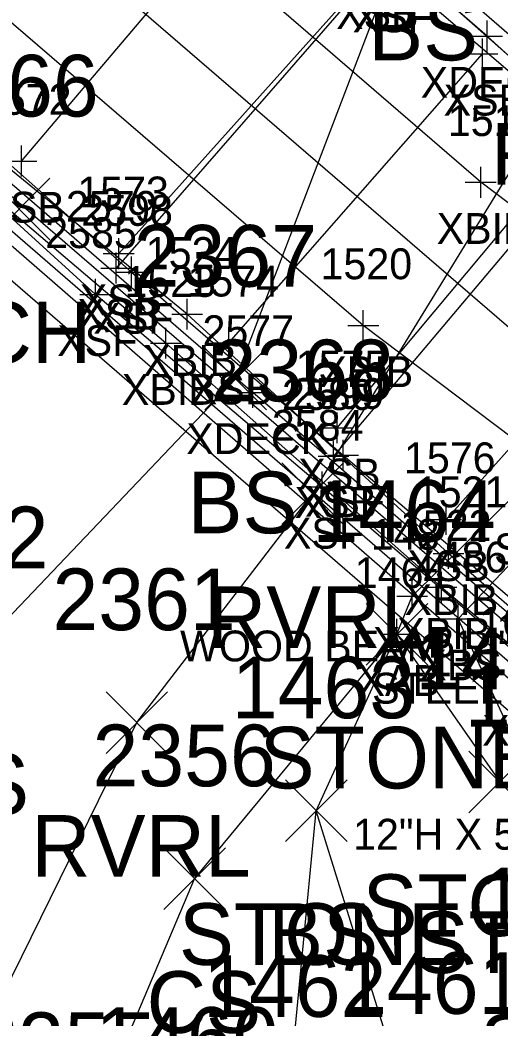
# Model space of a CAD drawing. Extents: x 1459992 to 1461532, y 647785 to 648535.
# Drawn here: x 1461331.07 to 1461346.66, y 648146.3 to 648178.67 of the extents above; entities that cross this region are included whole.
import ezdxf

# ---------------------------------------------------------------- set-up
doc = ezdxf.new("R2010")
doc.units = 0
for name, color, linetype in [('B_A', 7, 'Continuous'), ('B_C', 7, 'Continuous'), ('B_I', 7, 'Continuous'), ('B_TIC', 7, 'Continuous'), ('BB', 7, 'Continuous'), ('BDEFAULT', 7, 'Continuous'), ('BELB', 7, 'Continuous'), ('BSE', 7, 'Continuous'), ('BSUBM', 7, 'Continuous'), ('L_A', 7, 'Continuous'), ('L_I', 7, 'Continuous'), ('L_TIC', 7, 'Continuous'), ('LASF', 7, 'Continuous'), ('LAWE', 7, 'Continuous'), ('LELB', 7, 'Continuous')]:
    doc.layers.add(name, color=color, linetype=linetype)

msp = doc.modelspace()

# ---------------------------------------------------------------- linework, layer by layer
at = {"layer": 'B_TIC'}
for p, q in [((1461346.247, 648178.153), (1461346.322, 648178.153)), ((1461346.094, 648177.574), (1461346.17, 648177.574)), ((1461331.123, 648174.098), (1461331.199, 648174.098)), ((1461346.037, 648173.409), (1461346.112, 648173.409)), ((1461334.283, 648171.093), (1461334.358, 648171.093)), ((1461334.203, 648170.626), (1461334.279, 648170.626)), ((1461334.699, 648170.496), (1461334.775, 648170.496)), ((1461333.527, 648169.773), (1461333.602, 648169.773)), ((1461336.509, 648169.128), (1461336.584, 648169.128)), ((1461342.226, 648168.764), (1461342.301, 648168.764)), ((1461335.813, 648168.189), (1461335.889, 648168.189)), ((1461337.857, 648168.203), (1461337.933, 648168.203)), ((1461338.635, 648166.593), (1461338.71, 648166.593)), ((1461338.635, 648166.593), (1461338.71, 648166.593)), ((1461341.375, 648165.445), (1461341.451, 648165.445)), ((1461341.257, 648164.521), (1461341.333, 648164.521)), ((1461341.567, 648164.557), (1461341.642, 648164.557)), ((1461340.885, 648163.524), (1461340.961, 648163.524)), ((1461344.918, 648162.471), (1461344.993, 648162.471)), ((1461344.992, 648161.367), (1461345.068, 648161.367)), ((1461344.992, 648161.367), (1461345.068, 648161.367)), ((1461344.759, 648160.272), (1461344.834, 648160.272)), ((1461344.759, 648160.272), (1461344.834, 648160.272)), ((1461343.814, 648159.987), (1461343.889, 648159.987)), ((1461345.304, 648159.251), (1461345.379, 648159.251)), ((1461343.317, 648158.745), (1461343.392, 648158.745))]:
    msp.add_line(p, q, dxfattribs=at)
for points in [[(1461346.243, 648177.653), (1461346.243, 648178.653)], [(1461345.743, 648178.153), (1461346.743, 648178.153)], [(1461346.091, 648177.074), (1461346.091, 648178.074)], [(1461345.591, 648177.574), (1461346.591, 648177.574)], [(1461331.12, 648173.598), (1461331.12, 648174.598)], [(1461330.62, 648174.098), (1461331.62, 648174.098)], [(1461346.033, 648172.909), (1461346.033, 648173.909)], [(1461345.533, 648173.409), (1461346.533, 648173.409)], [(1461334.279, 648170.593), (1461334.279, 648171.593)], [(1461334.2, 648170.126), (1461334.2, 648171.126)], [(1461333.779, 648171.093), (1461334.779, 648171.093)], [(1461334.696, 648169.996), (1461334.696, 648170.996)], [(1461333.7, 648170.626), (1461334.7, 648170.626)], [(1461334.196, 648170.496), (1461335.196, 648170.496)], [(1461333.523, 648169.273), (1461333.523, 648170.273)], [(1461333.023, 648169.773), (1461334.023, 648169.773)], [(1461336.505, 648168.628), (1461336.505, 648169.628)], [(1461342.222, 648168.264), (1461342.222, 648169.264)], [(1461336.005, 648169.128), (1461337.005, 648169.128)], [(1461335.81, 648167.689), (1461335.81, 648168.689)], [(1461337.854, 648167.703), (1461337.854, 648168.703)], [(1461341.722, 648168.764), (1461342.722, 648168.764)], [(1461335.31, 648168.189), (1461336.31, 648168.189)], [(1461337.354, 648168.203), (1461338.354, 648168.203)], [(1461338.631, 648166.093), (1461338.631, 648167.093)], [(1461338.631, 648166.093), (1461338.631, 648167.093)], [(1461338.131, 648166.593), (1461339.131, 648166.593)], [(1461338.131, 648166.593), (1461339.131, 648166.593)], [(1461341.372, 648164.945), (1461341.372, 648165.945)], [(1461340.872, 648165.445), (1461341.872, 648165.445)], [(1461341.254, 648164.021), (1461341.254, 648165.021)], [(1461341.563, 648164.057), (1461341.563, 648165.057)], [(1461340.754, 648164.521), (1461341.754, 648164.521)], [(1461341.063, 648164.557), (1461342.063, 648164.557)], [(1461340.882, 648163.024), (1461340.882, 648164.024)], [(1461340.382, 648163.524), (1461341.382, 648163.524)], [(1461344.914, 648161.971), (1461344.914, 648162.971)], [(1461344.414, 648162.471), (1461345.414, 648162.471)], [(1461344.989, 648160.867), (1461344.989, 648161.867)], [(1461344.989, 648160.867), (1461344.989, 648161.867)], [(1461344.489, 648161.367), (1461345.489, 648161.367)], [(1461344.489, 648161.367), (1461345.489, 648161.367)], [(1461344.755, 648159.772), (1461344.755, 648160.772)], [(1461344.755, 648159.772), (1461344.755, 648160.772)], [(1461343.81, 648159.487), (1461343.81, 648160.487)], [(1461344.255, 648160.272), (1461345.255, 648160.272)], [(1461344.255, 648160.272), (1461345.255, 648160.272)], [(1461343.31, 648159.987), (1461344.31, 648159.987)], [(1461345.3, 648158.751), (1461345.3, 648159.751)], [(1461343.313, 648158.245), (1461343.313, 648159.245)], [(1461344.8, 648159.251), (1461345.8, 648159.251)], [(1461342.813, 648158.745), (1461343.813, 648158.745)]]:
    msp.add_lwpolyline(points, dxfattribs=at)
at = {"layer": 'BB'}
for points in [[(1461294.86, 648223.307), (1461364.242, 648163.24)], [(1461361.208, 648165.406), (1461348.067, 648176.515), (1461326.978, 648195.119), (1461323.429, 648198.068), (1461312.601, 648206.996), (1461302.604, 648215.891), (1461300.353, 648217.975)], [(1461357.803, 648164.521), (1461346.033, 648173.409), (1461325.183, 648191.393), (1461321.182, 648194.832), (1461311.295, 648203.276), (1461301.649, 648211.621), (1461295.127, 648216.651)], [(1461285.13, 648212.323), (1461354.607, 648152.433)], [(1461353.847, 648159.998), (1461342.222, 648168.764), (1461326.194, 648182.545), (1461313.236, 648193.724), (1461305.462, 648200.447), (1461296.007, 648208.646)], [(1461344.989, 648161.367), (1461336.505, 648169.128), (1461323.353, 648179.892), (1461310.889, 648191.178), (1461301.256, 648198.966), (1461293.739, 648205.641), (1461291.431, 648207.823)], [(1461344.755, 648160.272), (1461335.81, 648168.189), (1461323.548, 648178.602), (1461310.231, 648190.693), (1461300.415, 648198.699), (1461293.114, 648204.901), (1461290.791, 648207.096)], [(1461331.12, 648174.098), (1461339.08, 648183.468)], [(1461342.984, 648180.7), (1461334.2, 648170.626)], [(1461334.279, 648171.093), (1461342.601, 648180.377)], [(1461337.854, 648168.203), (1461346.091, 648177.574)], [(1461349.917, 648174.793), (1461341.254, 648164.521)], [(1461341.372, 648165.445), (1461349.214, 648174.817)], [(1461344.914, 648162.471), (1461352.982, 648171.505)], [(1461344.989, 648161.367), (1461352.704, 648154.677)], [(1461344.755, 648160.272), (1461352.306, 648153.966)]]:
    msp.add_lwpolyline(points, dxfattribs=at)
at = {"layer": 'BDEFAULT'}
for points in [[(1461360.363, 648157.144), (1461288.944, 648218.654)], [(1461360.571, 648165.346), (1461356.744, 648168.633), (1461349.668, 648174.685), (1461343.126, 648180.28), (1461343.115, 648180.272), (1461336.161, 648186.32), (1461329.105, 648192.44), (1461321.703, 648198.993), (1461314.797, 648204.994), (1461308.017, 648210.912), (1461301.203, 648216.737)], [(1461354.171, 648150.001), (1461282.953, 648211.596)], [(1461353.858, 648151.867), (1461350.867, 648153.898), (1461289.362, 648207.393), (1461287.217, 648209.127), (1461285.016, 648211.458)], [(1461353.858, 648151.867), (1461285.016, 648211.458)], [(1461350.543, 648155.26), (1461340.882, 648163.524), (1461333.523, 648169.773), (1461327.173, 648175.537), (1461320.082, 648181.72), (1461312.683, 648188.203), (1461305.743, 648194.222), (1461298.88, 648200.08), (1461289.091, 648208.417)], [(1461292.894, 648206.723), (1461299.511, 648201.164), (1461306.374, 648195.289), (1461313.277, 648189.283), (1461320.68, 648182.814), (1461327.748, 648176.637), (1461334.696, 648170.496), (1461341.563, 648164.557), (1461348.45, 648158.681)]]:
    msp.add_lwpolyline(points, dxfattribs=at)
at = {"layer": 'BELB'}
for points in [[(1461362.021, 648164.506), (1461356.918, 648168.766), (1461356.744, 648168.633), (1461346.243, 648178.153), (1461335.102, 648187.79), (1461324.925, 648196.655), (1461312.315, 648207.599), (1461296.583, 648221.232), (1461287.57, 648210.913), (1461301.391, 648198.959), (1461310.883, 648190.676), (1461320.988, 648181.882), (1461328.312, 648175.511), (1461338.631, 648166.593)], [(1461362.021, 648164.506), (1461353.03, 648154.158), (1461338.631, 648166.593)]]:
    msp.add_lwpolyline(points, dxfattribs=at)
at = {"layer": 'BSE'}
msp.add_lwpolyline([(1461348.313, 648152.755), (1461345.3, 648159.251), (1461356.511, 648171.05), (1461358.069, 648170.693), (1461360.685, 648169.084)], dxfattribs=at)
at = {"layer": 'BSUBM'}
msp.add_lwpolyline([(1461343.313, 648158.745), (1461343.81, 648159.987), (1461348.075, 648164.185), (1461352.541, 648168.868), (1461355.396, 648172.261), (1461357.111, 648173.632), (1461360.685, 648169.084)], dxfattribs=at)
at = {"layer": 'L_TIC'}
for points in [[(1461330.042, 648171.541), (1461332.042, 648173.541)], [(1461332.042, 648171.541), (1461330.042, 648173.541)], [(1461337.075, 648166.022), (1461339.075, 648168.022)], [(1461339.075, 648166.022), (1461337.075, 648168.022)], [(1461339.573, 648162.303), (1461341.573, 648164.303)], [(1461341.573, 648162.303), (1461339.573, 648164.303)], [(1461342.313, 648157.745), (1461344.313, 648159.745)], [(1461344.313, 648157.745), (1461342.313, 648159.745)], [(1461333.868, 648154.88), (1461335.868, 648156.88)], [(1461335.868, 648154.88), (1461333.868, 648156.88)], [(1461345.652, 648152.959), (1461347.652, 648154.959)], [(1461347.652, 648152.959), (1461345.652, 648154.959)], [(1461339.693, 648152.022), (1461341.693, 648154.022)], [(1461341.693, 648152.022), (1461339.693, 648154.022)], [(1461339.693, 648152.022), (1461341.693, 648154.022)], [(1461341.693, 648152.022), (1461339.693, 648154.022)], [(1461335.745, 648149.816), (1461337.745, 648151.816)], [(1461337.745, 648149.816), (1461335.745, 648151.816)]]:
    msp.add_lwpolyline(points, dxfattribs=at)
at = {"layer": 'LASF'}
msp.add_lwpolyline([(1461357.363, 648126.063), (1461352.841, 648127.816), (1461345.016, 648130.302), (1461339.468, 648139.304), (1461339.761, 648143.336), (1461340.693, 648153.022), (1461343.313, 648158.745), (1461346.652, 648153.959), (1461348.313, 648152.755), (1461350.456, 648149.42), (1461354.207, 648147.646)], dxfattribs=at)
at = {"layer": 'LAWE'}
msp.add_lwpolyline([(1461220.159, 648021.615), (1461235.47, 648039.294), (1461252.966, 648048.327), (1461267.663, 648064.216), (1461276.22, 648071.524), (1461288.833, 648087.698), (1461307.75, 648107.551), (1461316.994, 648127.784), (1461326.453, 648138.792), (1461334.868, 648155.88), (1461340.573, 648163.303), (1461349.799, 648178.335), (1461354.706, 648199.541), (1461353.8, 648220.98), (1461352.341, 648246.452), (1461354.078, 648262.219), (1461358.254, 648276.136), (1461371.394, 648295.376), (1461381.983, 648319.016), (1461394.178, 648330.617), (1461418.251, 648335.818), (1461440.86, 648338.789), (1461464.612, 648337.5), (1461486.388, 648342.471)], dxfattribs=at)
at = {"layer": 'LELB'}
for points in [[(1461216.735, 648025.379), (1461232.531, 648043.682), (1461249.111, 648052.696), (1461265.41, 648068.573), (1461273.176, 648074.771), (1461285.769, 648090.042), (1461304.003, 648110.191), (1461314.102, 648129.874), (1461321.787, 648141.876), (1461329.36, 648157.887), (1461338.075, 648167.022), (1461343.94, 648182.363), (1461347.487, 648202.693), (1461348.844, 648222.98), (1461349.522, 648245.94), (1461349.946, 648262.877), (1461353.497, 648277.365), (1461366.77, 648299.226), (1461380.277, 648319.065), (1461391.623, 648332.953), (1461418.599, 648338.961), (1461441.306, 648340.652), (1461465.695, 648340.733), (1461485.923, 648346.235)], [(1461336.745, 648150.816), (1461343.313, 648158.745)], [(1461254.788, 648024.689), (1461270.014, 648044.048), (1461286.662, 648058.61), (1461302.708, 648076.47), (1461318.859, 648092.871), (1461331.511, 648115.53), (1461340.274, 648126.529), (1461345.016, 648130.302), (1461347.542, 648139.28), (1461343.673, 648143.434), (1461340.693, 648153.022)], [(1461222.105, 648019.642), (1461239.41, 648035.454), (1461252.966, 648048.327), (1461269.635, 648062.753), (1461277.559, 648070.159), (1461291.696, 648084.237), (1461310.278, 648105.504), (1461323.636, 648123.883), (1461332.795, 648141.481), (1461336.745, 648150.816)]]:
    msp.add_lwpolyline(points, dxfattribs=at)

# ---------------------------------------------------------------- texts
at = {"layer": 'B_A'}
for s, p in [('XSB', (1461341.337, 648178.377)), ('XSF', (1461341.875, 648178.272)), ('XSF', (1461341.886, 648178.28)), ('XDECK', (1461344.086, 648176.153)), ('XSB', (1461344.827, 648175.574)), ('XSB', (1461329.856, 648172.098)), ('XBIB', (1461344.604, 648171.409)), ('XSB', (1461333.016, 648169.093)), ('XSB', (1461332.936, 648168.626)), ('XSF', (1461333.455, 648168.496)), ('XSF', (1461332.283, 648167.773)), ('XBIB', (1461335.076, 648167.128)), ('XBIB', (1461340.793, 648166.764)), ('XSB', (1461336.59, 648166.203)), ('XBIB', (1461334.381, 648166.189)), ('XDECK', (1461336.474, 648164.593)), ('XDECK', (1461336.474, 648164.593)), ('XSB', (1461340.108, 648163.445)), ('XSB', (1461339.99, 648162.521)), ('XSF', (1461340.323, 648162.557)), ('XSF', (1461339.642, 648161.524)), ('XSB', (1461343.65, 648160.471)), ('XBIB', (1461343.559, 648159.367)), ('XBIB', (1461343.559, 648159.367)), ('XBIB', (1461343.326, 648158.272)), ('XBIB', (1461343.326, 648158.272)), ('XAB', (1461342.531, 648157.987)), ('XBS', (1461344.04, 648157.251)), ('XAB', (1461342.034, 648156.745)), ('XAB', (1461346.08, 648155.13))]:
    msp.add_text(s, height=1, dxfattribs=at).set_placement(p)
at = {"layer": 'B_C'}
for s, p in [('STEEL IBEAM 2\'10"H X 1\'4"W X', (1461346.465, 648161.021)), ('WOOD BEAM 14"H X 9"W', (1461336.272, 648157.867)), ('WOOD BEAM 14"H X 9"W', (1461336.272, 648157.867)), ('STEEL IBEAM 2\'10"H X 1\'4"W X', (1461342.508, 648156.498)), ('12"H X 5"W WOOD ARCH', (1461341.889, 648151.76))]:
    msp.add_text(s, height=1, dxfattribs=at).set_placement(p)
at = {"layer": 'B_I'}
for s, p in [('1572', (1461329.773, 648175.598)), ('1519', (1461344.966, 648174.909)), ('1573', (1461332.933, 648172.593)), ('2579', (1461332.566, 648172.126)), ('2598', (1461333.066, 648171.996)), ('2585', (1461331.894, 648171.273)), ('1524', (1461335.159, 648170.628)), ('1520', (1461340.832, 648170.264)), ('1523', (1461334.464, 648169.689)), ('1574', (1461336.508, 648169.703)), ('2577', (1461337.001, 648168.093)), ('2577', (1461337.001, 648168.093)), ('1575', (1461340.025, 648166.945)), ('2580', (1461339.58, 648166.021)), ('2599', (1461339.93, 648166.057)), ('2584', (1461339.252, 648165.024)), ('1576', (1461343.54, 648163.971)), ('1521', (1461343.926, 648162.867)), ('1521', (1461343.926, 648162.867)), ('1522', (1461343.409, 648161.772)), ('1522', (1461343.409, 648161.772)), ('1487', (1461342.464, 648161.487)), ('1486', (1461343.926, 648160.751)), ('1464', (1461341.943, 648160.245)), ('1689', (1461345.986, 648158.63)), ('1690', (1461346.547, 648158.426))]:
    msp.add_text(s, height=1, dxfattribs=at).set_placement(p)
at = {"layer": 'L_A'}
for s, p in [('BS', (1461342.381, 648177.363)), ('RVRL', (1461346.366, 648173.335)), ('CH', (1461329.531, 648167.541)), ('BS', (1461336.516, 648162.022)), ('RVRL', (1461337.14, 648158.303)), ('STONE', (1461338.857, 648153.745)), ('BS', (1461327.8, 648152.887)), ('RVRL', (1461331.435, 648150.88)), ('STONE', (1461342.195, 648148.959)), ('STONE', (1461336.236, 648148.022)), ('BS', (1461339.134, 648148.022)), ('STONE', (1461343.856, 648147.755)), ('CS', (1461335.186, 648145.816)), ('STONE', (1461345.999, 648144.42))]:
    msp.add_text(s, height=2, dxfattribs=at).set_placement(p)
at = {"layer": 'L_I'}
for s, p in [('2366', (1461327.68, 648175.541)), ('2367', (1461334.768, 648170.022)), ('2368', (1461337.266, 648166.303)), ('1464', (1461340.573, 648161.745)), ('2362', (1461326.052, 648160.887)), ('2361', (1461332.128, 648158.88)), ('1465', (1461343.912, 648156.959)), ('1463', (1461337.953, 648156.022)), ('1463', (1461337.953, 648156.022)), ('1466', (1461345.517, 648155.755)), ('2356', (1461333.43, 648153.816)), ('1468', (1461346.003, 648149.179)), ('1461', (1461341.5, 648146.434)), ('1461', (1461341.5, 648146.434)), ('1462', (1461337.021, 648146.336)), ('2355', (1461329.535, 648144.481)), ('1460', (1461333.52, 648144.65))]:
    msp.add_text(s, height=2, dxfattribs=at).set_placement(p)

doc.saveas('drawing.dxf')
